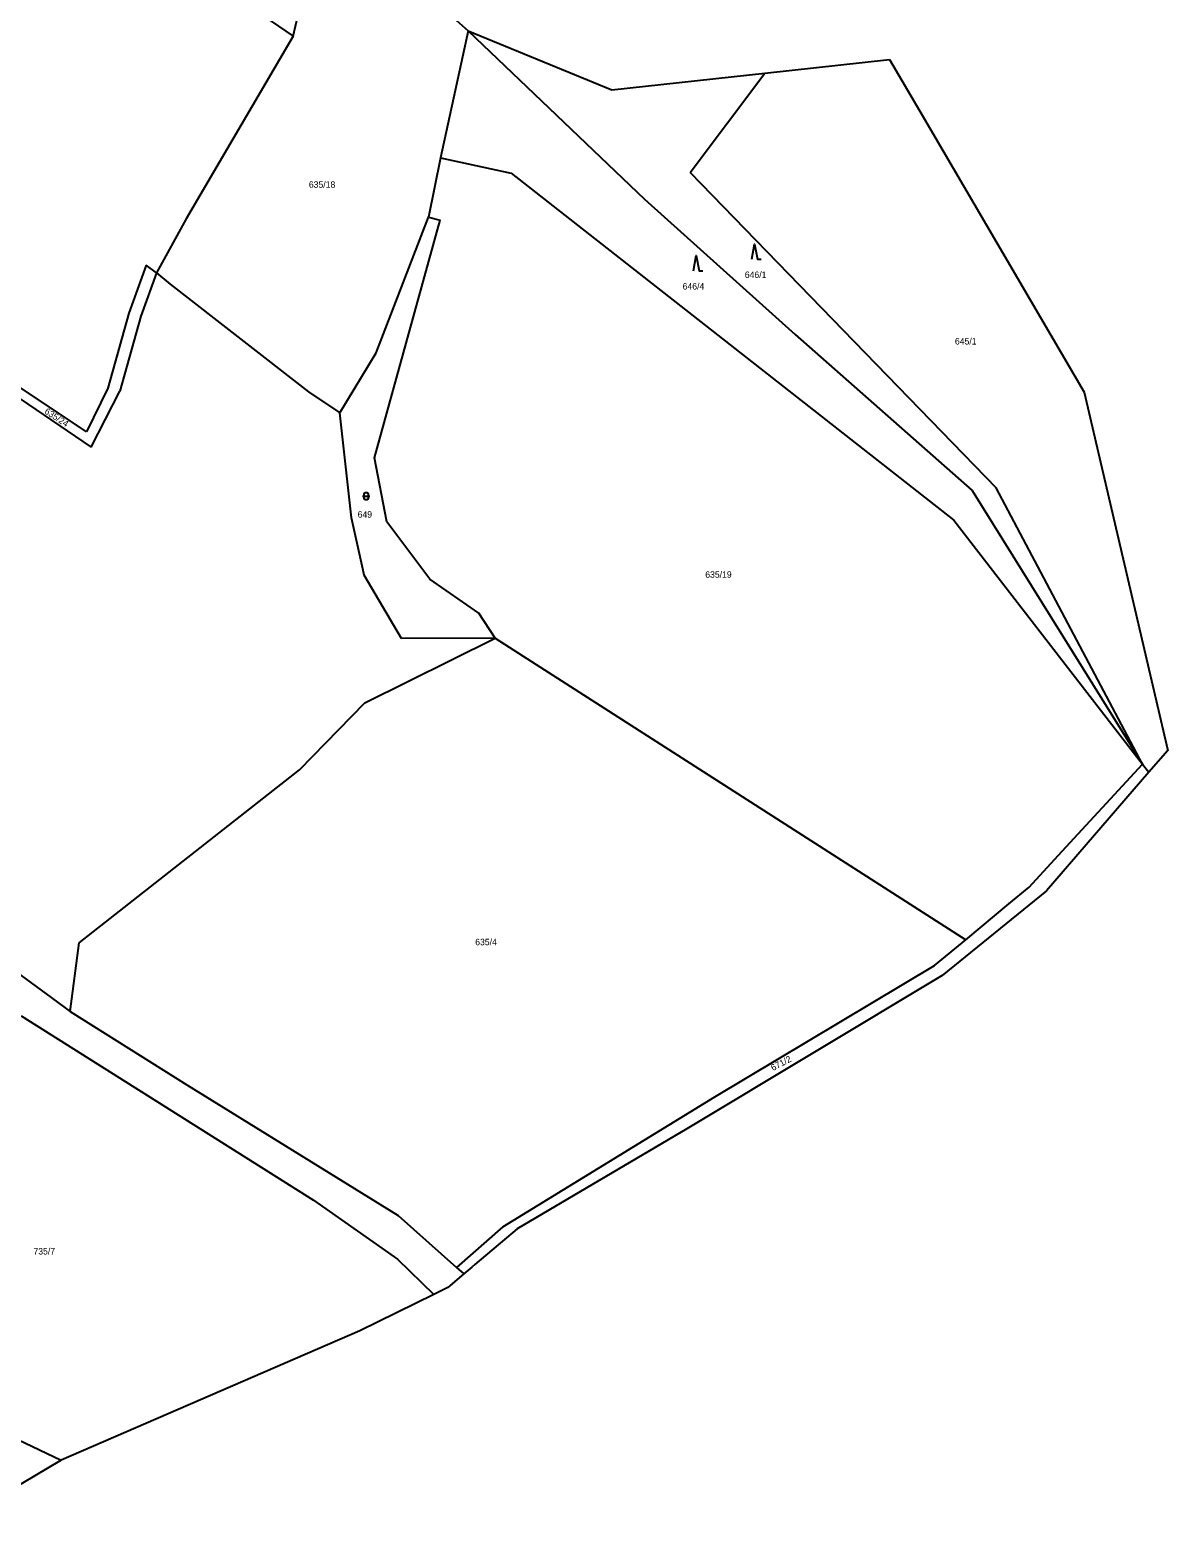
# Model space of a CAD drawing. Extents: x -801907 to -800293, y -1016964 to -1015684.
# Drawn here: x -800592.1 to -800292.7, y -1016529.8 to -1016132.8 of the extents above; entities that cross this region are included whole.
import ezdxf

# ---------------------------------------------------------------- set-up
doc = ezdxf.new("R2010")
doc.units = 0
for name, color, linetype in [('Default', 7, 'Continuous'), ('KN_HRANICE', 7, 'Continuous'), ('KN_KULTURY', 7, 'Continuous'), ('KN_PARCELY', 7, 'Continuous')]:
    doc.layers.add(name, color=color, linetype=linetype)

# ---------------------------------------------------------------- blocks, each defined once
blk = doc.blocks.new('308')
at = {"layer": 'Default'}
blk.add_lwpolyline([(-0.75, 0), (0, 4), (0.75, 0), (1.75, 0)], dxfattribs=at)
blk = doc.blocks.new('316')
at = {"layer": 'Default'}
for points in [[(-1, 1), (0.27, 1), (1, 1)], [(-0.5, 1.5), (-0.4, 1.79), (-0.15, 1.97), (0.16, 1.97), (0.41, 1.79), (0.51, 1.5), (0.51, 0.5), (0.41, 0.21), (0.16, 0.03), (-0.15, 0.03), (-0.4, 0.21), (-0.5, 0.5), (-0.5, 1.5)]]:
    blk.add_lwpolyline(points, dxfattribs=at)

msp = doc.modelspace()

# ---------------------------------------------------------------- linework, layer by layer
at = {"layer": 'KN_HRANICE'}
for p, q in [((-800583.45, -1016093.02), (-800522.87, -1016134.41)), ((-800522.87, -1016134.41), (-800514.57, -1016099.34)), ((-800514.57, -1016099.34), (-800476.81, -1016132.98)), ((-800522.87, -1016134.41), (-800551.03, -1016182.5)), ((-800476.81, -1016132.98), (-800484.08, -1016166.43)), ((-800476.81, -1016132.98), (-800430.4, -1016177.34)), ((-800476.81, -1016132.98), (-800438.98, -1016148.57)), ((-800398.74, -1016144.16), (-800365.91, -1016140.56)), ((-800365.91, -1016140.56), (-800357.93, -1016154.2)), ((-800438.98, -1016148.57), (-800398.74, -1016144.16)), ((-800418.39, -1016170.35), (-800398.74, -1016144.16)), ((-800357.93, -1016154.2), (-800314.69, -1016228.12)), ((-800484.08, -1016166.43), (-800487.25, -1016182.06)), ((-800484.08, -1016166.43), (-800465.5, -1016170.5)), ((-800465.5, -1016170.5), (-800348.97, -1016261.86)), ((-800418.39, -1016170.35), (-800337.86, -1016253.33)), ((-800430.4, -1016177.34), (-800390.73, -1016212.98)), ((-800551.03, -1016182.5), (-800558.79, -1016196.69)), ((-800500.98, -1016217.75), (-800487.25, -1016182.06)), ((-800494.95, -1016221.91), (-800484.2, -1016182.83)), ((-800487.25, -1016182.06), (-800484.2, -1016182.83)), ((-800561.5, -1016194.71), (-800566.11, -1016207.34)), ((-800558.79, -1016196.69), (-800561.5, -1016194.71)), ((-800558.79, -1016196.69), (-800562.97, -1016208.17)), ((-800558.79, -1016196.69), (-800555.25, -1016199.72)), ((-800555.25, -1016199.72), (-800518.84, -1016228.06)), ((-800566.11, -1016207.34), (-800571.65, -1016227.08)), ((-800562.97, -1016208.17), (-800568.51, -1016227.91)), ((-800390.73, -1016212.98), (-800344.13, -1016254.03)), ((-800577.22, -1016238.6), (-800606.39, -1016219.1)), ((-800510.56, -1016233.59), (-800500.98, -1016217.75)), ((-800608.51, -1016220.58), (-800576, -1016242.64)), ((-800501.41, -1016245.4), (-800494.95, -1016221.91)), ((-800571.65, -1016227.08), (-800577.22, -1016238.6)), ((-800576, -1016242.64), (-800568.51, -1016227.91)), ((-800518.84, -1016228.06), (-800510.56, -1016233.59)), ((-800314.69, -1016228.12), (-800292.66, -1016322.45)), ((-800507.51, -1016261.26), (-800510.56, -1016233.59)), ((-800498.19, -1016262.25), (-800501.41, -1016245.4)), ((-800344.13, -1016254.03), (-800299.37, -1016326.05)), ((-800299.37, -1016326.05), (-800337.86, -1016253.33)), ((-800504.56, -1016274.66), (-800507.51, -1016261.26)), ((-800486.92, -1016277.34), (-800498.19, -1016262.25)), ((-800348.97, -1016261.86), (-800299.37, -1016326.05)), ((-800504.2, -1016276.31), (-800504.56, -1016274.66)), ((-800494.36, -1016293.03), (-800504.2, -1016276.31)), ((-800474.03, -1016286.32), (-800486.92, -1016277.34)), ((-800469.66, -1016292.91), (-800474.03, -1016286.32)), ((-800504.02, -1016309.97), (-800469.66, -1016292.91)), ((-800469.66, -1016292.91), (-800494.36, -1016293.03)), ((-800469.66, -1016292.91), (-800463.57, -1016296.82)), ((-800463.57, -1016296.82), (-800345.86, -1016372.29)), ((-800521.22, -1016327.59), (-800504.02, -1016309.97)), ((-800292.66, -1016322.45), (-800297.63, -1016328.2)), ((-800321.54, -1016350.15), (-800299.37, -1016326.05)), ((-800299.37, -1016326.05), (-800297.63, -1016328.2)), ((-800579.14, -1016373.12), (-800521.22, -1016327.59)), ((-800297.63, -1016328.2), (-800324.6, -1016359.41)), ((-800329.19, -1016358.47), (-800321.54, -1016350.15)), ((-800334.53, -1016362.89), (-800329.19, -1016358.47)), ((-800324.6, -1016359.41), (-800352.02, -1016381.76)), ((-800345.86, -1016372.29), (-800334.53, -1016362.89)), ((-800612.1, -1016368.85), (-800587.87, -1016386.56)), ((-800581.56, -1016391.18), (-800579.14, -1016373.12)), ((-800354.03, -1016379.06), (-800345.86, -1016372.29)), ((-800352.02, -1016381.76), (-800419.23, -1016422.11)), ((-800411.92, -1016413.64), (-800354.03, -1016379.06)), ((-800587.87, -1016386.56), (-800581.56, -1016391.18)), ((-800594.45, -1016392.36), (-800517.53, -1016440.89)), ((-800581.56, -1016391.18), (-800550.86, -1016410.54)), ((-800550.86, -1016410.54), (-800495.19, -1016444.87)), ((-800467.63, -1016447.9), (-800411.92, -1016413.64)), ((-800419.23, -1016422.11), (-800463.93, -1016448.4)), ((-800517.53, -1016440.89), (-800495.36, -1016456.4)), ((-800495.19, -1016444.87), (-800479.84, -1016458.63)), ((-800467.63, -1016447.9), (-800479.84, -1016458.63)), ((-800463.93, -1016448.4), (-800475.04, -1016457.82)), ((-800495.36, -1016456.4), (-800485.85, -1016465.68)), ((-800475.04, -1016457.82), (-800475.85, -1016458.51)), ((-800477.97, -1016460.3), (-800482.16, -1016463.86)), ((-800479.84, -1016458.63), (-800477.97, -1016460.3)), ((-800475.85, -1016458.51), (-800477.97, -1016460.3)), ((-800485.85, -1016465.68), (-800505.3, -1016475.3)), ((-800483.37, -1016464.46), (-800485.85, -1016465.68)), ((-800482.16, -1016463.86), (-800483.37, -1016464.46)), ((-800658.32, -1016473.75), (-800583.94, -1016509.31)), ((-800505.3, -1016475.3), (-800583.94, -1016509.31)), ((-800583.94, -1016509.31), (-800618.21, -1016529.77))]:
    msp.add_line(p, q, dxfattribs=at)

# ---------------------------------------------------------------- block references
at = {"layer": 'KN_KULTURY'}
for name, p in [('308', (-800416.75, -1016196.16)), ('308', (-800401.4, -1016193.14)), ('316', (-800503.64, -1016256.54))]:
    msp.add_blockref(name, p, dxfattribs=at)

# ---------------------------------------------------------------- texts
at = {"layer": 'KN_PARCELY'}
for s, p in [('635/18', (-800518.72, -1016174.34)), ('646/1', (-800403.99, -1016198.08)), ('646/4', (-800420.35, -1016201.15)), ('645/1', (-800348.69, -1016215.6)), ('649', (-800505.88, -1016261.19)), ('635/19', (-800414.4, -1016277.01)), ('635/4', (-800474.94, -1016373.76)), ('735/7', (-800591.2, -1016455.18))]:
    msp.add_text(s, height=1.7, dxfattribs=at).set_placement(p)
for s, rotation, p in [('635/24', 326.987, (-800588.48, -1016233.6)), ('671/2', 27.674, (-800396.58, -1016406.9))]:
    msp.add_text(s, height=1.7, rotation=rotation, dxfattribs=at).set_placement(p)

doc.saveas('drawing.dxf')
